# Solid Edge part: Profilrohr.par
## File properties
Username: bmolnar
Dokumentum tartalom típus: 0
Author: bmolnar
Last saved by: bmolnar
Revision: 78
Sűrűség: 0,000 kg/m^3
Pontosság: 0,990
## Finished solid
Body 1: solid body, 59 faces, 170 edges, 112 vertices.
  Faces by surface: plane 30, cylinder 29
  Edges by curve: line 112, circle 58
Bounding box of the edges (mm): 40.000 x 29.000 x 40.000, from (-20, -9.5, -20) to (20, 19.5, 20).
Cylindrical faces by radius (mm): R0.2 x12, R0.5 x12, R5 x4, R12.5 x1
Planar faces by outward normal: +x 7, +y 1, +z 7, -x 7, -y 1, -z 7
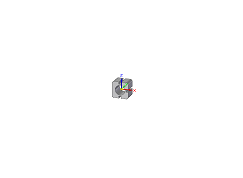
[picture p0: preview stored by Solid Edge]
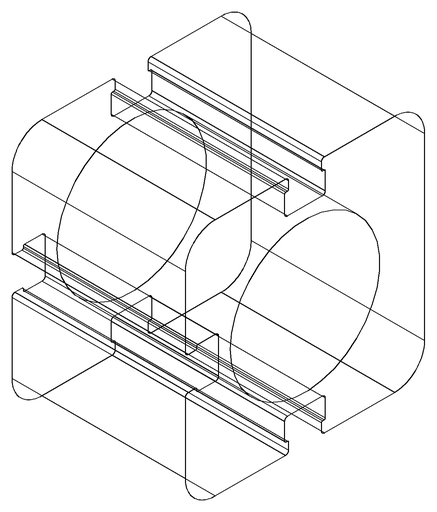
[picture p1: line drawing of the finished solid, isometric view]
